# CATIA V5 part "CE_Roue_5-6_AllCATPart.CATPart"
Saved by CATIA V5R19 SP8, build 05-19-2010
Part number: CE11_Roue_5-6_AllCATPart
Bounding box of the stored display mesh (mm): x -82.524 to -56.618, y 120.547 to 143.118, z 113.013 to 129.196
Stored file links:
  D:\Documents\1_Travail\1 - ac-limoges.fr\ac-limoges.fr\Emmanuel Maynard - STI2D_Turgot\2 -2I2D\1_SEQUENCE_ Tapis_de_course\3- Spécificités\Spé_ITEC\3-Pente\Tapis_TC520B_Pente\CE_Roue_5-6_AllCATPart.CATPart
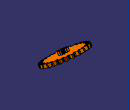
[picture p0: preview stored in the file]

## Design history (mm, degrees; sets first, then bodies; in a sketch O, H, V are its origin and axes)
AxisSystem1: origin (0, 0, 0), X (1, 0, 0), Y (0, 1, 0), Z (0, 0, 1)
Body1 (main body)
Body2 "Roue_6.1\\Corps principal"
  Solid1: solid without history
Body3 "Roue_5.1\\Corps principal"
  Solid2 "Solide.1": solid without history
